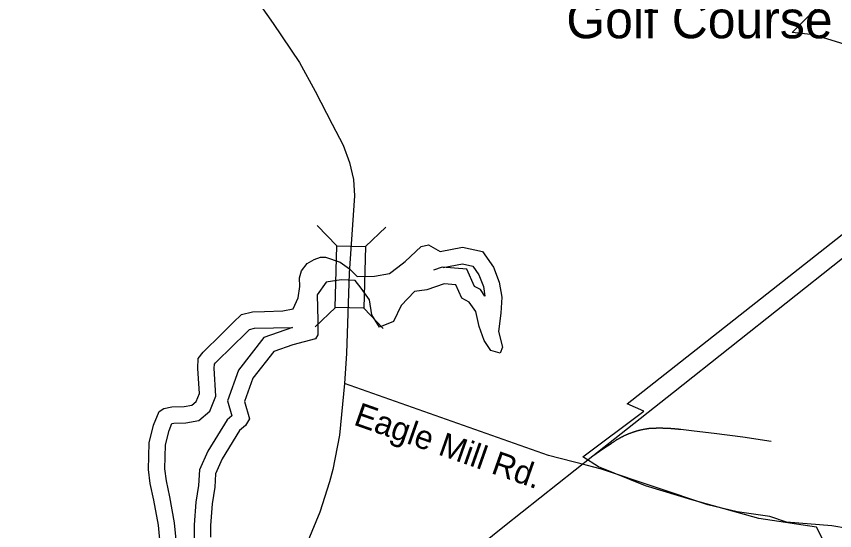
# Model space of a CAD drawing. Extents: x 1364363 to 1407445, y 538563 to 573342.
# Drawn here: x 1382486 to 1385775, y 548010 to 550075 of the extents above; entities that cross this region are included whole.
import ezdxf

# ---------------------------------------------------------------- set-up
doc = ezdxf.new("R2010")
doc.units = 0
for name, color, linetype in [('Exist Boundary Political City Limit New', 7, 'Continuous'), ('Exist Cultural Recreational Golf Course CELL', 7, 'Continuous'), ('Exist Hydrographic Buffer Line', 7, 'Continuous'), ('Exist Hydrographic Creek Double Shore', 7, 'Continuous'), ('Exist Railroad Mainline', 7, 'Continuous'), ('Exist Railroad Switch Yard', 7, 'Continuous'), ('Exist Road Secondary Structure Standard Bridge CELL', 7, 'Continuous'), ('Exist Road Secondary Type 51 Attributed', 7, 'Continuous'), ('Exist Road Secondary Type 51 Label', 7, 'Continuous')]:
    doc.layers.add(name, color=color, linetype=linetype)

msp = doc.modelspace()

# ---------------------------------------------------------------- linework, layer by layer
at = {"layer": 'Exist Boundary Political City Limit New'}
msp.add_lwpolyline([(1386030, 547384.7), (1385702.4, 548024.7), (1385471.1, 548058.8), (1385200.9, 548133.9), (1385014.9, 548190.4), (1384825.6, 548266.9), (1384763.5, 548306.2), (1385007.8, 548489.6), (1384941.6, 548520.2), (1386127.1, 549452.3), (1386509, 549750.2), (1385691.1, 550000.7), (1385605, 550011.1), (1385730.1, 550137), (1384990.9, 551732.2), (1384733.6, 552351.8), (1384320.9, 553308.2), (1383639.1, 552778.5), (1383439.1, 553038.9), (1383521, 553127.3), (1383078.1, 553192.4), (1382763.9, 552834.5), (1382486.2, 553789.1)], dxfattribs=at)
at = {"layer": 'Exist Hydrographic Buffer Line'}
for points in [[(1384201.6, 549067.3), (1384279.2, 549081.7), (1384320.9, 549073), (1384345.2, 549037.5), (1384363.4, 548990.6), (1384369.8, 548952.5), (1384351.2, 548978), (1384327.8, 548991.1), (1384297.4, 549060.6), (1384198, 549067.7), (1384163.3, 549056.2)], [(1383131, 547946.2), (1383122.1, 548041.6), (1383103.5, 548146.1), (1383089.3, 548210.3), (1383083.4, 548259.2), (1383085.4, 548354.8), (1383099.8, 548412.9), (1383111.4, 548440.7), (1383118.7, 548442.2), (1383167.5, 548443.7), (1383219.6, 548452.6), (1383264.1, 548489.7), (1383288.5, 548550.5), (1383281.8, 548662.7), (1383282.1, 548678.2), (1383286.4, 548683.6), (1383357.2, 548753.2), (1383403.9, 548799.6), (1383423.8, 548818.6), (1383443.8, 548823.8), (1383595.9, 548825.9)], [(1383595.9, 548825.9), (1383481, 548785.9), (1383379, 548655.3), (1383334.9, 548531.8), (1383352.1, 548471.7), (1383333.3, 548455.6), (1383255.3, 548329.3), (1383222, 548254.3), (1383218.1, 548191.8), (1383208.1, 548125.3), (1383201.1, 548033.8), (1383201.1, 547972), (1383234.3, 547887.1), (1383250.3, 547825.5), (1383246.5, 547789.4), (1383211.4, 547735.3), (1383168.7, 547667.6), (1383170.5, 547582.5), (1383136.8, 547533.4), (1383117.1, 547383.7), (1383126.2, 547269.9), (1383249.8, 547141)]]:
    msp.add_lwpolyline(points, dxfattribs=at)
at = {"layer": 'Exist Hydrographic Creek Double Shore'}
for points in [[(1383483, 548890), (1383557.1, 548892.6), (1383599.3, 548901.6), (1383618.3, 548945.5), (1383625.2, 548991.3), (1383624, 549025.8), (1383632.5, 549053.6), (1383655.2, 549082.6), (1383683.5, 549098.5), (1383708.1, 549108.4), (1383728.2, 549108.4), (1383788.4, 549088.4), (1383825.1, 549061.6), (1383856.2, 549031), (1383926.1, 549032.8), (1383986.4, 549042.3), (1384019.1, 549068.3), (1384049.2, 549091.7), (1384112.7, 549151.9), (1384142.8, 549158.6), (1384189.6, 549131.9)], [(1383483, 548890), (1383557.1, 548892.6), (1383599.3, 548901.6), (1383618.3, 548945.5), (1383625.2, 548991.3), (1383624, 549025.8), (1383632.5, 549053.6), (1383655.2, 549082.6), (1383683.5, 549098.5), (1383708.1, 549108.4), (1383728.2, 549108.4), (1383788.4, 549088.4), (1383825.1, 549061.6), (1383856.2, 549031), (1383926.1, 549032.8), (1383986.4, 549042.3), (1384019.1, 549068.3), (1384049.2, 549091.7), (1384112.7, 549151.9), (1384142.8, 549158.6), (1384189.6, 549131.9)], [(1384189.6, 549131.9), (1384279.9, 549148.6), (1384360.2, 549131.9), (1384403.7, 549068.3), (1384427.1, 549008.1), (1384437.1, 548947.8), (1384433.7, 548884.2), (1384423.7, 548810.6), (1384440.4, 548747), (1384430.4, 548723.6), (1384393.6, 548733.7), (1384366.9, 548773.8), (1384346.8, 548830.7), (1384333.4, 548890.9), (1384306.7, 548927.7), (1384276.6, 548944.5), (1384253.2, 548998), (1384206.4, 549001.4), (1384136.1, 548977.9), (1384086, 548971.2), (1384032.5, 548914.4), (1384002.4, 548850.8), (1383945.5, 548827.3), (1383915.4, 548877.5), (1383905.4, 548937.8), (1383872, 548984.6), (1383848.5, 549014.7), (1383791.7, 549018.1), (1383731.5, 549008.1), (1383694.7, 548957.9), (1383698.1, 548854.1), (1383698.1, 548797.2), (1383688, 548780.5), (1383597.7, 548757.1), (1383520.8, 548730.3), (1383437.2, 548623.2), (1383403.8, 548529.5), (1383423.9, 548459.3), (1383407.1, 548432.5), (1383383.7, 548412.4), (1383313.5, 548298.6), (1383286.7, 548238.4), (1383283.4, 548184.9), (1383273.4, 548117.9), (1383266.7, 548031.3), (1383266.7, 547984.4)], [(1384189.6, 549131.9), (1384279.9, 549148.6), (1384360.2, 549131.9), (1384403.7, 549068.3), (1384427.1, 549008.1), (1384437.1, 548947.8), (1384433.7, 548884.2), (1384423.7, 548810.6), (1384440.4, 548747), (1384430.4, 548723.6), (1384393.6, 548733.7), (1384366.9, 548773.8), (1384346.8, 548830.7), (1384333.4, 548890.9), (1384306.7, 548927.7), (1384276.6, 548944.5), (1384253.2, 548998), (1384206.4, 549001.4), (1384136.1, 548977.9), (1384086, 548971.2), (1384032.5, 548914.4), (1384002.4, 548850.8), (1383945.5, 548827.3), (1383915.4, 548877.5), (1383905.4, 548937.8), (1383872, 548984.6), (1383848.5, 549014.7), (1383791.7, 549018.1), (1383731.5, 549008.1), (1383694.7, 548957.9), (1383698.1, 548854.1), (1383698.1, 548797.2), (1383688, 548780.5), (1383597.7, 548757.1), (1383520.8, 548730.3), (1383437.2, 548623.2), (1383403.8, 548529.5), (1383423.9, 548459.3), (1383407.1, 548432.5), (1383383.7, 548412.4), (1383313.5, 548298.6), (1383286.7, 548238.4), (1383283.4, 548184.9), (1383273.4, 548117.9), (1383266.7, 548031.3), (1383266.7, 547984.4)], [(1383065.2, 547944.8), (1383057, 548032.8), (1383039.2, 548133.3), (1383024.5, 548199.2), (1383017.7, 548256), (1383019.9, 548363.5), (1383037.3, 548433.6), (1383060.5, 548489), (1383078.8, 548500.9), (1383111, 548507.7), (1383161, 548509.1), (1383191.1, 548514.3), (1383209.4, 548529.5), (1383222.1, 548561.2), (1383216.1, 548661.4), (1383217, 548701.6), (1383237.5, 548727.5), (1383311.1, 548799.9), (1383358, 548846.5), (1383390.7, 548877.9), (1383435, 548889.3), (1383483, 548890)]]:
    msp.add_lwpolyline(points, dxfattribs=at)
at = {"layer": 'Exist Railroad Mainline'}
for points in [[(1384802.7, 548310.4), (1384891.1, 548380.1), (1385126.9, 548566), (1385806.5, 549104.5), (1386537.2, 549679.1)], [(1384091, 547741.2), (1384448.2, 548030), (1384802.7, 548310.4)]]:
    msp.add_lwpolyline(points, dxfattribs=at)
at = {"layer": 'Exist Railroad Switch Yard'}
for points in [[(1384877.6, 548360.7), (1384879, 548361.7), (1384880.2, 548362.7), (1384881.8, 548363.7), (1384883.1, 548364.6), (1384884.5, 548365.6), (1384885.9, 548366.6), (1384887.2, 548367.5), (1384888.7, 548368.4), (1384890.1, 548369.4), (1384891.5, 548370.3), (1384892.9, 548371.2), (1384894.4, 548372.1), (1384895.7, 548373), (1384897.2, 548373.9), (1384898.6, 548374.8), (1384900, 548375.7), (1384901.5, 548376.6), (1384903, 548377.5), (1384904.3, 548378.3), (1384905.9, 548379.2), (1384907.4, 548380), (1384908.8, 548380.8), (1384910.3, 548381.7), (1384911.7, 548382.5), (1384913.3, 548383.3), (1384914.8, 548384.1), (1384916.1, 548384.9), (1384917.7, 548385.7), (1384919.1, 548386.5), (1384920.6, 548387.2), (1384922.1, 548388.1), (1384923.6, 548388.8), (1384925.2, 548389.5), (1384926.8, 548390.3), (1384928.2, 548391.1), (1384929.8, 548391.8), (1384931.2, 548392.5), (1384932.7, 548393.2), (1384934.4, 548394), (1384935.9, 548394.6), (1384937.4, 548395.3), (1384939, 548396), (1384940.5, 548396.7), (1384942, 548397.3), (1384943.6, 548398), (1384945.1, 548398.6), (1384946.8, 548399.3), (1384948.2, 548400), (1384949.9, 548400.6), (1384951.4, 548401.2), (1384953, 548401.8), (1384954.6, 548402.4), (1384956.1, 548403), (1384957.8, 548403.5), (1384959.4, 548404.2), (1384960.8, 548404.8), (1384962.5, 548405.3), (1384964.1, 548405.9), (1384965.8, 548406.4), (1384967.3, 548406.9), (1384968.8, 548407.4), (1384970.5, 548408), (1384972.1, 548408.5), (1384973.8, 548409), (1384975.4, 548409.5), (1384977, 548410), (1384978.7, 548410.5), (1384980.2, 548410.9), (1384981.9, 548411.4), (1384983.5, 548411.9), (1384985.1, 548412.3), (1384986.8, 548412.8), (1384988.4, 548413.2), (1384990, 548413.6), (1384991.6, 548414.1), (1384993.2, 548414.5), (1384994.9, 548414.8), (1384996.5, 548415.2), (1384998.2, 548415.6), (1384999.9, 548416), (1385001.5, 548416.4), (1385003.1, 548416.7), (1385004.7, 548417.1), (1385006.4, 548417.4), (1385008.1, 548417.7), (1385009.7, 548418.1), (1385011.4, 548418.4), (1385013.1, 548418.7), (1385014.8, 548418.9), (1385016.4, 548419.2), (1385018, 548419.5), (1385019.8, 548419.8), (1385021.4, 548420.1), (1385023, 548420.3), (1385024.7, 548420.6), (1385026.3, 548420.8), (1385028.1, 548421.1), (1385029.7, 548421.2), (1385031.4, 548421.5)], [(1385031.4, 548421.5), (1385032.7, 548421.6), (1385034, 548421.6), (1385035.3, 548421.7), (1385036.5, 548421.7), (1385037.7, 548421.8), (1385039, 548421.9), (1385040.3, 548421.9), (1385041.5, 548422), (1385042.9, 548422), (1385044.1, 548422.1), (1385045.4, 548422.1), (1385046.6, 548422.2), (1385047.9, 548422.3), (1385049.1, 548422.3), (1385050.3, 548422.3), (1385051.7, 548422.4), (1385053, 548422.4), (1385054.2, 548422.5), (1385055.5, 548422.5), (1385056.8, 548422.5), (1385058, 548422.5), (1385059.3, 548422.6), (1385060.5, 548422.6), (1385061.9, 548422.6), (1385063.2, 548422.6), (1385064.4, 548422.6), (1385065.6, 548422.6), (1385066.8, 548422.6), (1385068.1, 548422.6), (1385069.4, 548422.6), (1385070.6, 548422.6), (1385072, 548422.6), (1385073.2, 548422.6), (1385074.5, 548422.6), (1385075.8, 548422.6), (1385077, 548422.6), (1385078.2, 548422.6), (1385079.5, 548422.6), (1385080.9, 548422.6), (1385082.1, 548422.6), (1385083.4, 548422.6), (1385084.6, 548422.5), (1385085.9, 548422.5), (1385087.1, 548422.5), (1385088.4, 548422.5), (1385089.7, 548422.4), (1385091, 548422.4), (1385092.3, 548422.3), (1385093.5, 548422.3), (1385094.7, 548422.3), (1385096, 548422.2), (1385097.3, 548422.1), (1385098.5, 548422), (1385099.9, 548422), (1385101.1, 548422), (1385102.4, 548421.9), (1385103.7, 548421.9), (1385104.9, 548421.8), (1385106.1, 548421.7), (1385107.3, 548421.7), (1385108.7, 548421.6), (1385110, 548421.5), (1385111.2, 548421.4), (1385112.5, 548421.4), (1385113.7, 548421.3), (1385115, 548421.2), (1385116.3, 548421.1), (1385117.5, 548421.1), (1385118.7, 548420.9), (1385120.2, 548420.9), (1385121.4, 548420.8), (1385122.6, 548420.7), (1385123.8, 548420.6), (1385125.1, 548420.5), (1385126.4, 548420.4), (1385127.6, 548420.3), (1385128.9, 548420.2), (1385130.1, 548420.1), (1385131.3, 548419.9), (1385132.8, 548419.8), (1385134, 548419.7), (1385135.2, 548419.6), (1385136.5, 548419.5), (1385137.8, 548419.4), (1385139, 548419.2), (1385140.3, 548419.1), (1385141.5, 548419), (1385142.7, 548418.8), (1385144, 548418.7), (1385145.3, 548418.6), (1385146.6, 548418.5), (1385147.8, 548418.3), (1385149.2, 548418.1), (1385150.4, 548418), (1385151.6, 548417.9), (1385152.9, 548417.7), (1385154.1, 548417.5), (1385155.3, 548417.4), (1385156.7, 548417.2)], [(1385156.7, 548417.2), (1385211, 548411.4), (1385291.2, 548402.1), (1385406.5, 548386.4), (1385519.7, 548370)], [(1384802.7, 548310.4), (1384843.1, 548339), (1384877.6, 548360.7)]]:
    msp.add_lwpolyline(points, dxfattribs=at)
at = {"layer": 'Exist Road Secondary Structure Standard Bridge CELL'}
for p, q in [((1383695.9, 549236.3), (1383773.9, 549154.2)), ((1383971.7, 549229.2), (1383889.6, 549151.3)), ((1383769.6, 548906.4), (1383687.6, 548828.4)), ((1383882.7, 548903.5), (1383960.7, 548821.4))]:
    msp.add_line(p, q, dxfattribs=at)
msp.add_lwpolyline([(1383889.6, 549151.3), (1383883.3, 548903.5), (1383767.5, 548906.4), (1383773.9, 549154.2)], close=True, dxfattribs=at)
at = {"layer": 'Exist Road Secondary Type 51 Attributed'}
for points in [[(1383181, 551455.5), (1383208.3, 551400.4), (1383264.7, 551286.6), (1383313.1, 551192.6), (1383346.4, 551127.2), (1383369.2, 551072.9), (1383384.3, 551002.4), (1383385.7, 550655), (1383384.3, 550497.2), (1383382.8, 550293.1), (1383393.3, 550250.6), (1383422.1, 550185.9), (1383450.9, 550143.3), (1383519, 550046.4), (1383624.2, 549890.7), (1383687, 549774.7), (1383755.1, 549642.5), (1383799.8, 549558.8), (1383825.5, 549488.3), (1383840.7, 549420.8), (1383845.2, 549354.7), (1383823.8, 549043.7)], [(1383823.8, 549043.7), (1383813.7, 548721.1), (1383805.3, 548601.2)], [(1383805.3, 548601.2), (1383784.9, 548393.5), (1383758.1, 548256), (1383744.9, 548206.2), (1383706.4, 548084.9), (1383658.1, 547968.1), (1383530.4, 547777.4), (1383334.3, 547489.6), (1383160.9, 547241.9)], [(1384776.8, 548273.2), (1384625.3, 548312.4), (1383805.3, 548601.2)], [(1385826.4, 548019.2), (1385764.2, 548030.2), (1385581.1, 548044.9), (1385515.2, 548066.9), (1385383.3, 548085.2), (1385266.1, 548114.5), (1384837.7, 548257.4), (1384776.8, 548273.2)]]:
    msp.add_lwpolyline(points, dxfattribs=at)

# ---------------------------------------------------------------- texts
at = {"layer": 'Exist Cultural Recreational Golf Course CELL'}
msp.add_text('Golf Course', height=150, dxfattribs=at).set_placement((1384696.8, 549987.5))
at = {"layer": 'Exist Road Secondary Type 51 Label'}
msp.add_text('Eagle Mill Rd.', height=95, rotation=340.598, dxfattribs=at).set_placement((1383837.7, 548436.9))

doc.saveas('drawing.dxf')
